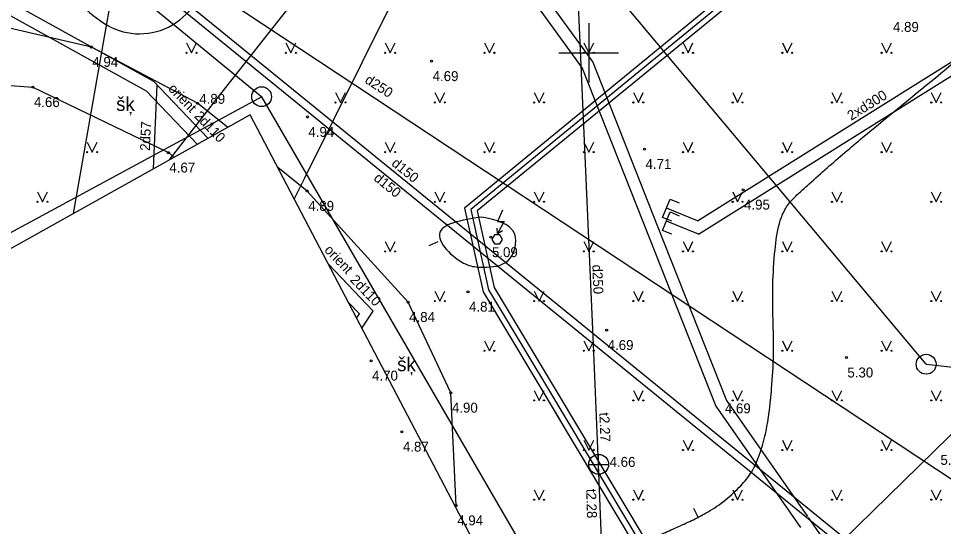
# Model space of a CAD drawing. Extents: x 519536 to 519949, y 326041 to 326519.
# Drawn here: x 519771.29 to 519817.86, y 326126.15 to 326151.73 of the extents above; entities that cross this region are included whole.
import ezdxf

# ---------------------------------------------------------------- set-up
doc = ezdxf.new("R2010")
doc.units = 0
for name, color, linetype in [('APGR_ELEM_####_####_#', 7, 'Continuous'), ('APGR_SARK_####_####_#', 7, 'Continuous'), ('CELI_CMAL_####_####_#', 7, 'Continuous'), ('CELI_CSEG_####_TKST_#', 7, 'Continuous'), ('CKOM_ELEM_####_####_#', 7, 'Continuous'), ('GEOD_ELEM_####_####_#', 7, 'Continuous'), ('RAMI_UZMR_####_####_#', 7, 'Continuous'), ('RELJ_AATZ_####_TKST_#', 7, 'Continuous'), ('RELJ_ELEM_####_####_#', 7, 'Continuous'), ('RELJ_HORZ_PAMT_####_#', 7, 'Continuous'), ('ROBZ_UZMR_####_####_#', 7, 'Continuous'), ('SAKT_VADP_NEDR_####_#', 7, 'Continuous'), ('SILT_ELEM_####_####_#', 7, 'Continuous'), ('SILT_VADP_NEDR_####_#', 7, 'Continuous'), ('SILT_VADP_NEDR_TKST_#', 7, 'Continuous'), ('SILT_VADP_UDEN_####_#', 7, 'Continuous'), ('SILT_VADP_UDEN_TKST_#', 7, 'Continuous'), ('SKAN_ELEM_####_####_#', 7, 'Continuous'), ('SKAN_ELEM_PAST_TKST_#', 7, 'Continuous'), ('SKAN_VADP_PAST_####_#', 7, 'Continuous'), ('SKAN_VADP_PAST_####_I', 7, 'Continuous'), ('SKAN_VADP_PAST_TKST_#', 7, 'Continuous'), ('SKAN_VADP_PAST_TKST_I', 7, 'Continuous'), ('TERT_ELEM_####_####_#', 7, 'Continuous'), ('UDTK_VADP_UDEN_####_#', 7, 'Continuous'), ('UDTK_VADP_UDEN_TKST_#', 7, 'Continuous')]:
    doc.layers.add(name, color=color, linetype=linetype)

msp = doc.modelspace()

# ---------------------------------------------------------------- linework, layer by layer
at = {"layer": 'APGR_ELEM_####_####_#'}
for centre in [(519783.53, 326147.79), (519816.99, 326134.32)]:
    msp.add_circle(centre, 0.5, dxfattribs=at)
at = {"layer": 'APGR_SARK_####_####_#'}
for p, q in [((519731.697, 326190.43), (519783.534, 326147.79)), ((519816.989, 326134.324), (519795.048, 326160.518)), ((519803.539, 326113.32), (519783.534, 326147.79)), ((519816.989, 326134.324), (519831.329, 326132.766))]:
    msp.add_line(p, q, dxfattribs=at)
at = {"layer": 'CELI_CMAL_####_####_#'}
for points in [[(519781.823, 326146.243), (519780.304, 326147.457), (519774.958, 326150.292), (519769.888, 326151.456), (519762.82, 326151.393), (519757.443, 326150.456), (519752.94, 326149.002), (519749.714, 326147.053), (519749.697, 326147.076), (519748.841, 326151.995), (519747.597, 326157.755), (519745.712, 326164.89), (519743.536, 326172.586), (519742.432, 326179.9), (519742.282, 326187.957), (519742.541, 326195.477)], [(519794.352, 326164.634), (519794.676, 326163.127), (519795.596, 326155.889), (519800.204, 326149.521), (519803.455, 326141.299)], [(519793.814, 326164.329), (519794.131, 326162.652), (519795.02, 326155.661), (519799.674, 326149.231), (519803.048, 326140.696)], [(519736.71, 326138.294), (519741.6, 326140.985), (519745.218, 326138.222), (519749.337, 326143.099), (519756.037, 326146.767), (519764.072, 326148.86), (519772.015, 326148.268), (519778.835, 326144.973), (519779.124, 326144.737)], [(519793.298, 326127.124), (519793.33, 326127.209), (519793.063, 326132.885), (519790.908, 326137.45), (519785.829, 326143.043), (519784.34, 326144.233)], [(519803.455, 326141.299), (519806.937, 326132.492), (519811.012, 326126.66)], [(519803.048, 326140.696), (519806.405, 326132.206), (519810.67, 326126.102)], [(519811.049, 326126.606), (519811.891, 326125.402), (519813.064, 326124.039)]]:
    msp.add_lwpolyline(points, dxfattribs=at)
at = {"layer": 'CKOM_ELEM_####_####_#'}
msp.add_line((519795.411, 326140.908), (519795.652, 326141.047), dxfattribs=at)
msp.add_lwpolyline([(519795.66, 326142.07), (519795.411, 326141.507), (519795.747, 326141.507), (519795.411, 326140.908), (519795.389, 326141.178)], dxfattribs=at)
msp.add_lwpolyline([(519795.255, 326140.378), (519795.521, 326140.378), (519795.654, 326140.608), (519795.521, 326140.839), (519795.255, 326140.839), (519795.122, 326140.608)], close=True, dxfattribs=at)
at = {"layer": 'GEOD_ELEM_####_####_#'}
for p, q in [((519800, 326151.5), (519800, 326150)), ((519798.5, 326150), (519800, 326150)), ((519800, 326150), (519800, 326148.5)), ((519800, 326150), (519801.5, 326150))]:
    msp.add_line(p, q, dxfattribs=at)
at = {"layer": 'RAMI_UZMR_####_####_#'}
msp.add_lwpolyline([(519873.021, 326209.453), (519881.37, 326184.273), (519884.229, 326177.508), (519883.353, 326172.044), (519868.284, 326155.201), (519831.787, 326123.789), (519817.117, 326113.183), (519808.359, 326108.08), (519804.649, 326107.204), (519795.685, 326122.565), (519782.956, 326146.875), (519761.4, 326134.85), (519741.243, 326123.664), (519728.435, 326146.148), (519720.513, 326144.604), (519669.064, 326119.018)], dxfattribs=at)
at = {"layer": 'RELJ_ELEM_####_####_#'}
for centre in [(519774.958, 326150.292), (519792.091, 326149.577), (519772.015, 326148.268), (519780.304, 326147.457), (519785.836, 326146.769), (519778.835, 326144.973), (519802.809, 326145.152), (519785.829, 326143.043), (519807.772, 326143.108), (519795.077, 326140.713), (519793.923, 326137.967), (519790.908, 326137.45), (519800.904, 326136.037), (519812.974, 326134.655), (519789.042, 326134.498), (519793.063, 326132.885), (519790.596, 326130.922), (519793.33, 326127.209)]:
    msp.add_circle(centre, 0.05, dxfattribs=at)
at = {"layer": 'RELJ_HORZ_PAMT_####_#'}
for p, q in [((519792.401, 326140.484), (519791.944, 326140.283)), ((519805.517, 326126.618), (519805.289, 326127.063))]:
    msp.add_line(p, q, dxfattribs=at)
for points in [[(519809.195, 326132.865), (519809.212, 326133.075), (519809.301, 326134.822), (519809.282, 326136.574), (519809.271, 326138.326), (519809.381, 326140.073), (519809.6, 326141.404), (519809.838, 326142.026), (519810.219, 326142.57), (519810.657, 326142.998), (519811.107, 326143.402), (519812.001, 326144.204), (519813.806, 326145.745), (519817.455, 326148.748), (519819.686, 326150.62), (519821.96, 326152.453), (519823.088, 326153.161), (519824.295, 326153.721), (519826.818, 326154.617), (519828.096, 326155.009), (519829.402, 326155.301), (519830.714, 326155.606), (519832.008, 326156.038), (519833.672, 326156.825), (519834.481, 326157.284), (519834.867, 326157.55), (519835.246, 326157.852), (519835.569, 326158.141), (519835.872, 326158.447), (519836.153, 326158.778), (519836.416, 326159.142), (519836.794, 326159.892), (519836.942, 326160.69), (519836.959, 326162.597)], [(519774.709, 326152.158), (519773.918, 326153.886), (519774.248, 326154.673), (519774.571, 326154.973), (519777.371, 326155.628), (519779.611, 326155.216), (519780.472, 326154.344), (519779.415, 326151.66), (519776.17, 326151.191), (519774.709, 326152.158)], [(519794.617, 326141.733), (519796.274, 326140.867), (519795.95, 326139.552), (519794.705, 326139.206), (519793.966, 326139.3), (519792.489, 326140.875), (519794.617, 326141.733)], [(519807.66, 326128.203), (519808.195, 326128.893), (519808.649, 326129.915), (519808.929, 326130.954), (519809.195, 326132.865)], [(519796.84, 326120.586), (519797.106, 326120.637), (519797.649, 326120.767), (519797.761, 326120.883), (519797.899, 326121.146), (519798, 326121.429), (519798.111, 326121.704), (519798.278, 326121.943), (519798.817, 326122.459), (519799.373, 326122.95), (519800.535, 326123.859), (519801.756, 326124.681), (519803.031, 326125.424), (519803.766, 326125.808), (519804.518, 326126.15), (519805.271, 326126.495), (519806.008, 326126.888), (519806.456, 326127.174), (519806.885, 326127.487), (519807.66, 326128.203)]]:
    msp.add_spline(points, degree=3, dxfattribs=at)
at = {"layer": 'ROBZ_UZMR_####_####_#'}
for p, q in [((519783.534, 326147.79), (519743.05, 326125.883)), ((519803.539, 326113.32), (519783.534, 326147.79))]:
    msp.add_line(p, q, dxfattribs=at)
at = {"layer": 'SAKT_VADP_NEDR_####_#'}
for p, q in [((519798.112, 326133.4), (519807.038, 326118.511)), ((519797.926, 326133.126), (519806.771, 326118.375)), ((519798.299, 326131.921), (519806.549, 326118.161))]:
    msp.add_line(p, q, dxfattribs=at)
for points in [[(519812.674, 326157.732), (519793.74, 326142.183), (519794.678, 326137.96), (519798.556, 326131.492)], [(519812.849, 326157.514), (519794.062, 326142.115), (519794.96, 326138.073), (519797.926, 326133.126)], [(519813.025, 326157.297), (519794.385, 326142.048), (519795.242, 326138.185), (519798.112, 326133.4)]]:
    msp.add_lwpolyline(points, dxfattribs=at)
at = {"layer": 'SILT_ELEM_####_####_#'}
for points in [[(519804.185, 326141.522), (519803.722, 326141.71), (519804.098, 326142.636), (519804.561, 326142.448)], [(519804.186, 326140.873), (519803.723, 326141.061), (519804.099, 326141.987), (519804.562, 326141.799)]]:
    msp.add_lwpolyline(points, dxfattribs=at)
at = {"layer": 'SILT_VADP_NEDR_####_#'}
msp.add_line((519778.09, 326144.16), (519778.264, 326148.385), dxfattribs=at)
for points in [[(519805.47, 326141.539), (519818.935, 326149.974)], [(519805.528, 326140.868), (519819.314, 326149.504)], [(519805.47, 326141.539), (519803.91, 326142.173)], [(519805.528, 326140.868), (519803.911, 326141.524)]]:
    msp.add_lwpolyline(points, dxfattribs=at)
at = {"layer": 'SILT_VADP_UDEN_####_#'}
for p, q in [((519734.128, 326172.924), (519778.089, 326148.567)), ((519733.877, 326172.376), (519777.719, 326148.087)), ((519778.089, 326148.567), (519780.837, 326145.693)), ((519777.719, 326148.087), (519780.296, 326145.391)), ((519786.891, 326139.36), (519789.152, 326136.995)), ((519787.896, 326137.44), (519788.455, 326136.856)), ((519788.575, 326136.144), (519789.152, 326136.995)), ((519788.312, 326136.646), (519788.455, 326136.856))]:
    msp.add_line(p, q, dxfattribs=at)
at = {"layer": 'SKAN_ELEM_####_####_#'}
for p, q in [((519800.501, 326128.781), (519800.501, 326129.781)), ((519800.001, 326129.281), (519801.001, 326129.281))]:
    msp.add_line(p, q, dxfattribs=at)
msp.add_circle((519800.501, 326129.281), 0.5, dxfattribs=at)
at = {"layer": 'SKAN_VADP_PAST_####_#'}
for p, q in [((519781.233, 326147.608), (519798.711, 326169.891)), ((519800.235, 326135.313), (519798.711, 326169.891)), ((519775.62, 326150.81), (519776.391, 326155.21)), ((519774.061, 326141.913), (519775.62, 326150.81)), ((519778.871, 326144.596), (519781.233, 326147.608)), ((519800.501, 326129.281), (519800.235, 326135.313)), ((519801.028, 326116.009), (519800.501, 326129.281))]:
    msp.add_line(p, q, dxfattribs=at)
at = {"layer": 'SKAN_VADP_PAST_####_I'}
msp.add_lwpolyline([(519818.452, 326128.4), (519775.066, 326157.076)], dxfattribs=at)
at = {"layer": 'TERT_ELEM_####_####_#'}
for p, q in [((519779.75, 326150.5), (519780, 326150)), ((519780, 326150), (519780.25, 326150.5)), ((519784.75, 326150.5), (519785, 326150)), ((519785, 326150), (519785.25, 326150.5)), ((519789.75, 326150.5), (519790, 326150)), ((519790, 326150), (519790.25, 326150.5)), ((519794.75, 326150.5), (519795, 326150)), ((519795, 326150), (519795.25, 326150.5)), ((519799.75, 326150.5), (519800, 326150)), ((519800, 326150), (519800.25, 326150.5)), ((519804.75, 326150.5), (519805, 326150)), ((519805, 326150), (519805.25, 326150.5)), ((519809.75, 326150.5), (519810, 326150)), ((519810, 326150), (519810.25, 326150.5)), ((519814.75, 326150.5), (519815, 326150)), ((519815, 326150), (519815.25, 326150.5)), ((519787.25, 326148), (519787.5, 326147.5)), ((519787.5, 326147.5), (519787.75, 326148)), ((519792.25, 326148), (519792.5, 326147.5)), ((519792.5, 326147.5), (519792.75, 326148)), ((519797.25, 326148), (519797.5, 326147.5)), ((519797.5, 326147.5), (519797.75, 326148)), ((519802.25, 326148), (519802.5, 326147.5)), ((519802.5, 326147.5), (519802.75, 326148)), ((519807.25, 326148), (519807.5, 326147.5)), ((519807.5, 326147.5), (519807.75, 326148)), ((519812.25, 326148), (519812.5, 326147.5)), ((519812.5, 326147.5), (519812.75, 326148)), ((519817.25, 326148), (519817.5, 326147.5)), ((519817.5, 326147.5), (519817.75, 326148)), ((519774.75, 326145.5), (519775, 326145)), ((519775, 326145), (519775.25, 326145.5)), ((519789.75, 326145.5), (519790, 326145)), ((519790, 326145), (519790.25, 326145.5)), ((519794.75, 326145.5), (519795, 326145)), ((519795, 326145), (519795.25, 326145.5)), ((519799.75, 326145.5), (519800, 326145)), ((519800, 326145), (519800.25, 326145.5)), ((519804.75, 326145.5), (519805, 326145)), ((519805, 326145), (519805.25, 326145.5)), ((519809.75, 326145.5), (519810, 326145)), ((519810, 326145), (519810.25, 326145.5)), ((519814.75, 326145.5), (519815, 326145)), ((519815, 326145), (519815.25, 326145.5)), ((519772.25, 326143), (519772.5, 326142.5)), ((519772.5, 326142.5), (519772.75, 326143)), ((519792.25, 326143), (519792.5, 326142.5)), ((519792.5, 326142.5), (519792.75, 326143)), ((519797.25, 326143), (519797.5, 326142.5)), ((519797.5, 326142.5), (519797.75, 326143)), ((519807.25, 326143), (519807.5, 326142.5)), ((519807.5, 326142.5), (519807.75, 326143)), ((519812.25, 326143), (519812.5, 326142.5)), ((519812.5, 326142.5), (519812.75, 326143)), ((519817.25, 326143), (519817.5, 326142.5)), ((519817.5, 326142.5), (519817.75, 326143)), ((519789.75, 326140.5), (519790, 326140)), ((519790, 326140), (519790.25, 326140.5)), ((519799.75, 326140.5), (519800, 326140)), ((519800, 326140), (519800.25, 326140.5)), ((519804.75, 326140.5), (519805, 326140)), ((519805, 326140), (519805.25, 326140.5)), ((519809.75, 326140.5), (519810, 326140)), ((519810, 326140), (519810.25, 326140.5)), ((519814.75, 326140.5), (519815, 326140)), ((519815, 326140), (519815.25, 326140.5)), ((519792.25, 326138), (519792.5, 326137.5)), ((519792.5, 326137.5), (519792.75, 326138)), ((519797.25, 326138), (519797.5, 326137.5)), ((519797.5, 326137.5), (519797.75, 326138)), ((519802.25, 326138), (519802.5, 326137.5)), ((519802.5, 326137.5), (519802.75, 326138)), ((519807.25, 326138), (519807.5, 326137.5)), ((519807.5, 326137.5), (519807.75, 326138)), ((519812.25, 326138), (519812.5, 326137.5)), ((519812.5, 326137.5), (519812.75, 326138)), ((519817.25, 326138), (519817.5, 326137.5)), ((519817.5, 326137.5), (519817.75, 326138)), ((519794.75, 326135.5), (519795, 326135)), ((519795, 326135), (519795.25, 326135.5)), ((519799.75, 326135.5), (519800, 326135)), ((519800, 326135), (519800.25, 326135.5)), ((519809.75, 326135.5), (519810, 326135)), ((519810, 326135), (519810.25, 326135.5)), ((519814.75, 326135.5), (519815, 326135)), ((519815, 326135), (519815.25, 326135.5)), ((519797.25, 326133), (519797.5, 326132.5)), ((519797.5, 326132.5), (519797.75, 326133)), ((519802.25, 326133), (519802.5, 326132.5)), ((519802.5, 326132.5), (519802.75, 326133)), ((519807.25, 326133), (519807.5, 326132.5)), ((519807.5, 326132.5), (519807.75, 326133)), ((519812.25, 326133), (519812.5, 326132.5)), ((519812.5, 326132.5), (519812.75, 326133)), ((519817.25, 326133), (519817.5, 326132.5)), ((519817.5, 326132.5), (519817.75, 326133)), ((519799.75, 326130.5), (519800, 326130)), ((519800, 326130), (519800.25, 326130.5)), ((519804.75, 326130.5), (519805, 326130)), ((519805, 326130), (519805.25, 326130.5)), ((519809.75, 326130.5), (519810, 326130)), ((519810, 326130), (519810.25, 326130.5)), ((519814.75, 326130.5), (519815, 326130)), ((519815, 326130), (519815.25, 326130.5)), ((519797.25, 326128), (519797.5, 326127.5)), ((519797.5, 326127.5), (519797.75, 326128)), ((519802.25, 326128), (519802.5, 326127.5)), ((519802.5, 326127.5), (519802.75, 326128)), ((519807.25, 326128), (519807.5, 326127.5)), ((519807.5, 326127.5), (519807.75, 326128)), ((519812.25, 326128), (519812.5, 326127.5)), ((519812.5, 326127.5), (519812.75, 326128)), ((519817.25, 326128), (519817.5, 326127.5)), ((519817.5, 326127.5), (519817.75, 326128))]:
    msp.add_line(p, q, dxfattribs=at)
for centre, radius in [((519779.75, 326150), 0.028), ((519780.25, 326150), 0.0263), ((519784.75, 326150), 0.028), ((519785.25, 326150), 0.0263), ((519789.75, 326150), 0.028), ((519790.25, 326150), 0.0263), ((519794.75, 326150), 0.028), ((519795.25, 326150), 0.0263), ((519799.75, 326150), 0.028), ((519800.25, 326150), 0.0263), ((519804.75, 326150), 0.028), ((519805.25, 326150), 0.0263), ((519809.75, 326150), 0.028), ((519810.25, 326150), 0.0263), ((519814.75, 326150), 0.028), ((519815.25, 326150), 0.0263), ((519787.25, 326147.5), 0.028), ((519787.75, 326147.5), 0.0263), ((519792.25, 326147.5), 0.028), ((519792.75, 326147.5), 0.0263), ((519797.25, 326147.5), 0.028), ((519797.75, 326147.5), 0.0263), ((519802.25, 326147.5), 0.028), ((519802.75, 326147.5), 0.0263), ((519807.25, 326147.5), 0.028), ((519807.75, 326147.5), 0.0263), ((519812.25, 326147.5), 0.028), ((519812.75, 326147.5), 0.0263), ((519817.25, 326147.5), 0.028), ((519817.75, 326147.5), 0.0263), ((519774.75, 326145), 0.028), ((519775.25, 326145), 0.0263), ((519789.75, 326145), 0.028), ((519790.25, 326145), 0.0263), ((519794.75, 326145), 0.028), ((519795.25, 326145), 0.0263), ((519799.75, 326145), 0.028), ((519800.25, 326145), 0.0263), ((519804.75, 326145), 0.028), ((519805.25, 326145), 0.0263), ((519809.75, 326145), 0.028), ((519810.25, 326145), 0.0263), ((519814.75, 326145), 0.028), ((519815.25, 326145), 0.0263), ((519772.25, 326142.5), 0.028), ((519772.75, 326142.5), 0.0263), ((519792.25, 326142.5), 0.028), ((519792.75, 326142.5), 0.0263), ((519797.25, 326142.5), 0.028), ((519797.75, 326142.5), 0.0263), ((519807.25, 326142.5), 0.028), ((519807.75, 326142.5), 0.0263), ((519812.25, 326142.5), 0.028), ((519812.75, 326142.5), 0.0263), ((519817.25, 326142.5), 0.028), ((519817.75, 326142.5), 0.0263), ((519789.75, 326140), 0.028), ((519790.25, 326140), 0.0263), ((519799.75, 326140), 0.028), ((519800.25, 326140), 0.0263), ((519804.75, 326140), 0.028), ((519805.25, 326140), 0.0263), ((519809.75, 326140), 0.028), ((519810.25, 326140), 0.0263), ((519814.75, 326140), 0.028), ((519815.25, 326140), 0.0263), ((519792.25, 326137.5), 0.028), ((519792.75, 326137.5), 0.0263), ((519797.25, 326137.5), 0.028), ((519797.75, 326137.5), 0.0263), ((519802.25, 326137.5), 0.028), ((519802.75, 326137.5), 0.0263), ((519807.25, 326137.5), 0.028), ((519807.75, 326137.5), 0.0263), ((519812.25, 326137.5), 0.028), ((519812.75, 326137.5), 0.0263), ((519817.25, 326137.5), 0.028), ((519817.75, 326137.5), 0.0263), ((519794.75, 326135), 0.028), ((519795.25, 326135), 0.0263), ((519799.75, 326135), 0.028), ((519800.25, 326135), 0.0263), ((519809.75, 326135), 0.028), ((519810.25, 326135), 0.0263), ((519814.75, 326135), 0.028), ((519815.25, 326135), 0.0263), ((519797.25, 326132.5), 0.028), ((519797.75, 326132.5), 0.0263), ((519802.25, 326132.5), 0.028), ((519802.75, 326132.5), 0.0263), ((519807.25, 326132.5), 0.028), ((519807.75, 326132.5), 0.0263), ((519812.25, 326132.5), 0.028), ((519812.75, 326132.5), 0.0263), ((519817.25, 326132.5), 0.028), ((519817.75, 326132.5), 0.0263), ((519799.75, 326130), 0.028), ((519800.25, 326130), 0.0263), ((519804.75, 326130), 0.028), ((519805.25, 326130), 0.0263), ((519809.75, 326130), 0.028), ((519810.25, 326130), 0.0263), ((519814.75, 326130), 0.028), ((519815.25, 326130), 0.0263), ((519797.25, 326127.5), 0.028), ((519797.75, 326127.5), 0.0263), ((519802.25, 326127.5), 0.028), ((519802.75, 326127.5), 0.0263), ((519807.25, 326127.5), 0.028), ((519807.75, 326127.5), 0.0263), ((519812.25, 326127.5), 0.028), ((519812.75, 326127.5), 0.0263), ((519817.25, 326127.5), 0.028), ((519817.75, 326127.5), 0.0263)]:
    msp.add_circle(centre, radius, dxfattribs=at)
at = {"layer": 'UDTK_VADP_UDEN_####_#'}
msp.add_line((519812.769, 326125.41), (519827.278, 326139.636), dxfattribs=at)
for points in [[(519785.714, 326143.712), (519798.711, 326169.891)], [(519767.203, 326162.23), (519778.16, 326153.314), (519799.72, 326135.77), (519812.588, 326125.299)], [(519767.47, 326162.528), (519778.412, 326153.624), (519799.945, 326136.103), (519812.913, 326125.551)], [(519785.178, 326142.632), (519785.714, 326143.712)]]:
    msp.add_lwpolyline(points, dxfattribs=at)

# ---------------------------------------------------------------- texts
at = {"layer": 'CELI_CSEG_####_TKST_#'}
for p in [(519776.209, 326147.075), (519790.354, 326133.972)]:
    msp.add_text('šķ', height=0.7, dxfattribs=at).set_placement(p)
at = {"layer": 'RELJ_AATZ_####_TKST_#'}
for s, p in [('4.89', (519815.32, 326151.055)), ('4.94', (519775.008, 326149.292)), ('4.69', (519792.141, 326148.577)), ('4.66', (519772.065, 326147.268)), ('4.89', (519780.391, 326147.433)), ('4.94', (519785.886, 326145.769)), ('4.67', (519778.885, 326143.973)), ('4.71', (519802.859, 326144.152)), ('4.89', (519785.879, 326142.043)), ('4.95', (519807.822, 326142.108)), ('5.09', (519795.127, 326139.713)), ('4.81', (519793.973, 326136.967)), ('4.84', (519790.958, 326136.45)), ('4.69', (519800.954, 326135.037)), ('5.30', (519813.024, 326133.655)), ('4.70', (519789.092, 326133.498)), ('4.90', (519793.113, 326131.885)), (' 4.69', (519806.671, 326131.849)), ('4.87', (519790.646, 326129.922)), ('4.94', (519793.38, 326126.209))]:
    msp.add_text(s, height=0.5, dxfattribs=at).set_placement(p)
at = {"layer": 'SILT_VADP_NEDR_TKST_#'}
for s, rotation, p in [('2xd300', 32.0651, (519813.215, 326146.568)), ('2d57', 87.5693, (519777.906, 326145.054))]:
    msp.add_text(s, height=0.5, rotation=rotation, dxfattribs=at).set_placement(p)
at = {"layer": 'SILT_VADP_UDEN_TKST_#'}
for s, rotation, p in [('orient', 313.7118, (519778.793, 326148.162)), ('2d110', 313.7118, (519780.11, 326146.784)), ('orient', 313.7108, (519786.657, 326140.038)), ('2d110', 313.7118, (519787.952, 326138.538))]:
    msp.add_text(s, height=0.5, rotation=rotation, dxfattribs=at).set_placement(p)
at = {"layer": 'SKAN_ELEM_PAST_TKST_#'}
for s, p in [(' 4.66', (519800.865, 326129.154)), ('5.05', (519817.71, 326129.255))]:
    msp.add_text(s, height=0.5, dxfattribs=at).set_placement(p)
at = {"layer": 'SKAN_VADP_PAST_TKST_#'}
for s, rotation, p in [('d250', 272.5238, (519800.177, 326139.327)), ('t2.27', 272.5238, (519800.533, 326131.883)), ('t2.28', 271.6304, (519799.875, 326128.041))]:
    msp.add_text(s, height=0.5, rotation=rotation, dxfattribs=at).set_placement(p)
at = {"layer": 'SKAN_VADP_PAST_TKST_I'}
msp.add_text('d250', height=0.5, rotation=327.0394, dxfattribs=at).set_placement((519788.685, 326148.521))
at = {"layer": 'UDTK_VADP_UDEN_TKST_#'}
for rotation, p in [(320.8654, (519790.03, 326144.364)), (320.8637, (519789.137, 326143.617))]:
    msp.add_text('d150', height=0.5, rotation=rotation, dxfattribs=at).set_placement(p)

doc.saveas('drawing.dxf')
